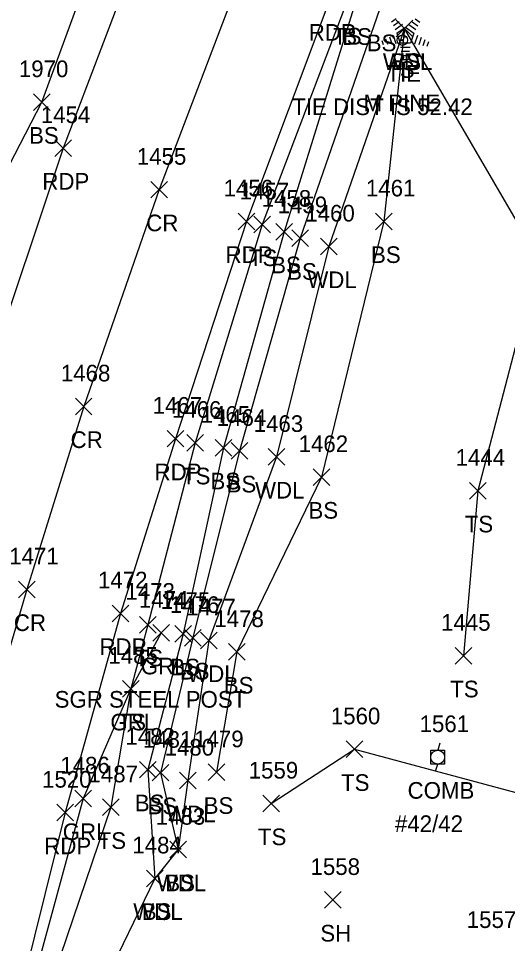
# Model space of a CAD drawing. Extents: x 1885914 to 1887218, y 756253 to 760620.
# Drawn here: x 1886460.8 to 1886519.5, y 759787.4 to 759898.5 of the extents above; entities that cross this region are included whole.
import ezdxf

# ---------------------------------------------------------------- set-up
doc = ezdxf.new("R2010")
doc.units = 0
for name, color, linetype in [('C_A', 7, 'Continuous'), ('C_C', 7, 'Continuous'), ('CBP', 7, 'Continuous'), ('L_A', 7, 'Continuous'), ('L_C', 7, 'Continuous'), ('L_I', 7, 'Continuous'), ('L_TIC', 7, 'Continuous'), ('LAWA', 7, 'Continuous'), ('LELB', 7, 'Continuous'), ('LTC', 7, 'Continuous'), ('P_A', 7, 'Continuous'), ('P_I', 7, 'Continuous'), ('P_TIC', 7, 'Continuous'), ('PET', 7, 'Continuous'), ('PRC', 7, 'Continuous'), ('R_A', 7, 'Continuous'), ('R_C', 7, 'Continuous'), ('R_I', 7, 'Continuous'), ('R_TIC', 7, 'Continuous'), ('RGR', 7, 'Continuous'), ('U_A', 7, 'Continuous'), ('U_C', 7, 'Continuous'), ('U_I', 7, 'Continuous'), ('UP', 7, 'Continuous')]:
    doc.layers.add(name, color=color, linetype=linetype)

msp = doc.modelspace()

# ---------------------------------------------------------------- linework, layer by layer
at = {"layer": 'CBP'}
for radius in [0.625, 0.0833]:
    msp.add_circle((1886506.91, 759895.92), radius, dxfattribs=at)
at = {"layer": 'L_TIC'}
for points in [[(1886506.15, 759896.34), (1886508.15, 759898.34)], [(1886508.15, 759896.34), (1886506.15, 759898.34)], [(1886506.15, 759896.34), (1886508.15, 759898.34)], [(1886508.15, 759896.34), (1886506.15, 759898.34)], [(1886462.57, 759887.48), (1886464.57, 759889.48)], [(1886464.57, 759887.48), (1886462.57, 759889.48)], [(1886489.04, 759872.78), (1886491.04, 759874.78)], [(1886491.04, 759872.78), (1886489.04, 759874.78)], [(1886503.69, 759873.15), (1886505.69, 759875.15)], [(1886505.69, 759873.15), (1886503.69, 759875.15)], [(1886491.69, 759871.91), (1886493.69, 759873.91)], [(1886493.69, 759871.91), (1886491.69, 759873.91)], [(1886493.61, 759871.13), (1886495.61, 759873.13)], [(1886495.61, 759871.13), (1886493.61, 759873.13)], [(1886497.06, 759870.13), (1886499.06, 759872.13)], [(1886499.06, 759870.13), (1886497.06, 759872.13)], [(1886481, 759846.55), (1886483, 759848.55)], [(1886483, 759846.55), (1886481, 759848.55)], [(1886484.39, 759845.95), (1886486.39, 759847.95)], [(1886486.39, 759845.95), (1886484.39, 759847.95)], [(1886486.33, 759845.58), (1886488.33, 759847.58)], [(1886488.33, 759845.58), (1886486.33, 759847.58)], [(1886490.77, 759844.85), (1886492.77, 759846.85)], [(1886492.77, 759844.85), (1886490.77, 759846.85)], [(1886496.17, 759842.43), (1886498.17, 759844.43)], [(1886498.17, 759842.43), (1886496.17, 759844.43)], [(1886514.99, 759840.78), (1886516.99, 759842.78)], [(1886516.99, 759840.78), (1886514.99, 759842.78)], [(1886475.31, 759824.69), (1886477.31, 759826.69)], [(1886477.31, 759824.69), (1886475.31, 759826.69)], [(1886479.56, 759823.59), (1886481.56, 759825.59)], [(1886481.56, 759823.59), (1886479.56, 759825.59)], [(1886480.7, 759823.1), (1886482.7, 759825.1)], [(1886482.7, 759823.1), (1886480.7, 759825.1)], [(1886482.62, 759822.8), (1886484.62, 759824.8)], [(1886484.62, 759822.8), (1886482.62, 759824.8)], [(1886485.99, 759821.41), (1886487.99, 759823.41)], [(1886487.99, 759821.41), (1886485.99, 759823.41)], [(1886513.24, 759820.96), (1886515.24, 759822.96)], [(1886515.24, 759820.96), (1886513.24, 759822.96)], [(1886473.25, 759816.99), (1886475.25, 759818.99)], [(1886475.25, 759816.99), (1886473.25, 759818.99)], [(1886500.13, 759809.72), (1886502.13, 759811.72)], [(1886502.13, 759809.72), (1886500.13, 759811.72)], [(1886475.3, 759807.27), (1886477.3, 759809.27)], [(1886477.3, 759807.27), (1886475.3, 759809.27)], [(1886476.83, 759806.91), (1886478.83, 759808.91)], [(1886478.83, 759806.91), (1886476.83, 759808.91)], [(1886483.57, 759806.96), (1886485.57, 759808.96)], [(1886485.57, 759806.96), (1886483.57, 759808.96)], [(1886480.1, 759805.96), (1886482.1, 759807.96)], [(1886482.1, 759805.96), (1886480.1, 759807.96)], [(1886470.86, 759802.75), (1886472.86, 759804.75)], [(1886472.86, 759802.75), (1886470.86, 759804.75)], [(1886490.13, 759803.2), (1886492.13, 759805.2)], [(1886492.13, 759803.2), (1886490.13, 759805.2)], [(1886478.96, 759797.66), (1886480.96, 759799.66)], [(1886480.96, 759797.66), (1886478.96, 759799.66)], [(1886478.96, 759797.66), (1886480.96, 759799.66)], [(1886480.96, 759797.66), (1886478.96, 759799.66)], [(1886476.13, 759794.21), (1886478.13, 759796.21)], [(1886478.13, 759794.21), (1886476.13, 759796.21)], [(1886476.13, 759794.21), (1886478.13, 759796.21)], [(1886478.13, 759794.21), (1886476.13, 759796.21)], [(1886497.55, 759791.62), (1886499.55, 759793.62)], [(1886499.55, 759791.62), (1886497.55, 759793.62)]]:
    msp.add_lwpolyline(points, dxfattribs=at)
at = {"layer": 'LAWA'}
msp.add_lwpolyline([(1886523.26, 759869.7), (1886507.15, 759897.34), (1886498.06, 759871.13), (1886491.77, 759845.85), (1886483.62, 759823.8), (1886481.1, 759806.96), (1886479.96, 759798.66), (1886477.13, 759795.21), (1886470.77, 759782.07), (1886465.64, 759760.08), (1886461.33, 759737.18), (1886457.67, 759707.39), (1886455.06, 759684.97), (1886454.35, 759663.94), (1886455.07, 759641.46), (1886456.61, 759622.06), (1886456.79, 759611.09), (1886458.12, 759603.52), (1886460.31, 759591.25), (1886468.58, 759565.01)], dxfattribs=at)
at = {"layer": 'LELB'}
for points in [[(1886725.27, 760338.09), (1886712.33, 760310.28), (1886698.46, 760286.41), (1886683.25, 760252.31), (1886665.56, 760220.6), (1886649.26, 760186.3), (1886631.93, 760155.48), (1886614.95, 760123.77), (1886599.48, 760094.94), (1886586.46, 760070.53), (1886572.04, 760041.07), (1886559.72, 760022.59), (1886545.87, 759996.97), (1886529.41, 759963.14), (1886510.6, 759921.25), (1886501.24, 759900.36), (1886492.69, 759872.91), (1886485.39, 759846.95), (1886480.56, 759824.59), (1886476.3, 759808.27), (1886477.13, 759795.21)], [(1886435.82, 759833.71), (1886443.92, 759843.16), (1886452.31, 759861.14), (1886457.66, 759877.13), (1886463.57, 759888.48), (1886474.59, 759918.53), (1886493.94, 759963.02), (1886508.21, 759990.58), (1886529.58, 760040.14)], [(1886559.72, 760022.59), (1886549.4, 759996.33), (1886532.08, 759961.59), (1886524, 759917.34), (1886512.94, 759920.8), (1886504.17, 759899.59), (1886494.61, 759872.13), (1886487.33, 759846.58), (1886481.7, 759824.1), (1886477.83, 759807.91), (1886479.96, 759798.66)], [(1886564.69, 760023.37), (1886556.81, 759992.84), (1886551.99, 759948.71), (1886542, 759918.15), (1886528.59, 759884.81), (1886523.26, 759869.7), (1886515.99, 759841.78), (1886514.24, 759821.96)], [(1886527.64, 759964.02), (1886508.85, 759921.99), (1886500.17, 759900.4), (1886490.04, 759873.78), (1886482, 759847.55), (1886476.31, 759825.69), (1886474.25, 759817.99), (1886471.86, 759803.75), (1886464.28, 759781.47), (1886459.74, 759761.62), (1886455.11, 759738.34), (1886453.91, 759709.07), (1886450.32, 759686.96), (1886450.55, 759665.25), (1886450.92, 759642.65), (1886453.45, 759622.64), (1886456.79, 759611.09)], [(1886507.15, 759897.34), (1886504.69, 759874.15), (1886497.17, 759843.43), (1886486.99, 759822.41), (1886484.57, 759807.96)], [(1886491.13, 759804.2), (1886501.13, 759810.72), (1886522.18, 759805.09), (1886544.57, 759789.63), (1886568.21, 759770.94), (1886581.11, 759761.41), (1886584.27, 759751.77)]]:
    msp.add_lwpolyline(points, dxfattribs=at)
at = {"layer": 'LTC'}
for p, q in [((1886505.61, 759898.13), (1886506.14, 759898.52)), ((1886505.82, 759897.67), (1886506.52, 759898.18)), ((1886506.03, 759897.2), (1886506.91, 759897.84)), ((1886508.06, 759898.14), (1886508.74, 759897.65)), ((1886508.43, 759898.49), (1886508.98, 759898.09)), ((1886506.25, 759896.75), (1886507.27, 759897.48)), ((1886506.25, 759896.75), (1886506.64, 759895.55)), ((1886507.27, 759897.48), (1886508.26, 759896.76)), ((1886507.69, 759897.79), (1886508.5, 759897.2)), ((1886508.26, 759896.76), (1886507.87, 759895.55)), ((1886504.43, 759895.88), (1886504.59, 759895.41)), ((1886504.89, 759896.09), (1886505.1, 759895.44)), ((1886505.34, 759896.31), (1886505.62, 759895.47)), ((1886505.8, 759896.53), (1886506.13, 759895.51)), ((1886508.7, 759896.48), (1886508.36, 759895.44)), ((1886509.15, 759896.23), (1886508.86, 759895.35)), ((1886509.59, 759895.98), (1886509.35, 759895.25)), ((1886510.03, 759895.73), (1886509.85, 759895.16)), ((1886507.87, 759895.55), (1886506.64, 759895.55)), ((1886507.83, 759895.05), (1886506.69, 759895.05)), ((1886507.75, 759894.55), (1886506.76, 759894.55)), ((1886507.67, 759894.05), (1886506.83, 759894.05)), ((1886507.58, 759893.55), (1886506.91, 759893.55))]:
    msp.add_line(p, q, dxfattribs=at)
at = {"layer": 'P_TIC'}
for points in [[(1886465.13, 759881.96), (1886467.13, 759883.96)], [(1886467.13, 759881.96), (1886465.13, 759883.96)], [(1886476.68, 759876.96), (1886478.68, 759878.96)], [(1886478.68, 759876.96), (1886476.68, 759878.96)], [(1886487.16, 759873.15), (1886489.16, 759875.15)], [(1886489.16, 759873.15), (1886487.16, 759875.15)], [(1886467.59, 759850.92), (1886469.59, 759852.92)], [(1886469.59, 759850.92), (1886467.59, 759852.92)], [(1886478.62, 759847.04), (1886480.62, 759849.04)], [(1886480.62, 759847.04), (1886478.62, 759849.04)], [(1886460.77, 759828.93), (1886462.77, 759830.93)], [(1886462.77, 759828.93), (1886460.77, 759830.93)], [(1886472, 759826.05), (1886474, 759828.05)], [(1886474, 759826.05), (1886472, 759828.05)], [(1886465.37, 759802.11), (1886467.37, 759804.11)], [(1886467.37, 759802.11), (1886465.37, 759804.11)]]:
    msp.add_lwpolyline(points, dxfattribs=at)
at = {"layer": 'PET'}
for points in [[(1886505.21, 759975.04), (1886485.32, 759931.76), (1886475.82, 759908.45), (1886466.13, 759882.96), (1886456.93, 759855.61), (1886449.99, 759833.06), (1886442.98, 759808.26), (1886435.87, 759778.49), (1886430.37, 759752.23), (1886424.92, 759721.57), (1886422.03, 759696.27), (1886420.3, 759670.71), (1886419.91, 759641.82), (1886421.23, 759616.47), (1886424.6, 759585.72), (1886430.09, 759554.32), (1886435.19, 759528.63), (1886443.72, 759490.84), (1886451.63, 759459.71), (1886459.13, 759429.12), (1886468.69, 759393.26), (1886479.71, 759351.07), (1886485.06, 759331.17)], [(1886526.14, 759964.92), (1886507.07, 759922.75), (1886498.17, 759900.86), (1886488.16, 759874.15), (1886479.62, 759848.04), (1886473, 759827.05), (1886466.37, 759803.11), (1886458.99, 759773.42), (1886453.36, 759746.97), (1886448.76, 759720.11), (1886445.71, 759693.61), (1886444.44, 759668.96), (1886443.78, 759643.55), (1886445.31, 759617.59), (1886448.26, 759589.04), (1886453.63, 759558.69), (1886458.27, 759533.55), (1886466.8, 759496), (1886474.35, 759464.49), (1886481.64, 759434.54), (1886491.18, 759398.8), (1886502.68, 759358.39), (1886508.23, 759337.95)]]:
    msp.add_lwpolyline(points, dxfattribs=at)
at = {"layer": 'PRC'}
msp.add_lwpolyline([(1886516.05, 759969.43), (1886496.99, 759926.69), (1886487.66, 759904.2), (1886477.68, 759877.96), (1886468.59, 759851.92), (1886461.77, 759829.93), (1886454.6, 759805.62), (1886447.16, 759775.82), (1886441.74, 759748.8), (1886436.89, 759720.56), (1886434.02, 759695.25), (1886432.32, 759669.09), (1886432.26, 759642.82), (1886433.77, 759616.6), (1886436.98, 759587.84), (1886441.74, 759556.93), (1886446.53, 759531.43), (1886454.86, 759493.34), (1886462.57, 759461.76), (1886470.69, 759431.8), (1886480.02, 759395.82), (1886491.53, 759354.96), (1886496.99, 759335.08)], dxfattribs=at)
at = {"layer": 'R_TIC'}
for points in [[(1886476.91, 759823.72), (1886478.91, 759825.72)], [(1886478.91, 759823.72), (1886476.91, 759825.72)], [(1886473.25, 759816.99), (1886475.25, 759818.99)], [(1886475.25, 759816.99), (1886473.25, 759818.99)], [(1886467.53, 759803.81), (1886469.53, 759805.81)], [(1886469.53, 759803.81), (1886467.53, 759805.81)]]:
    msp.add_lwpolyline(points, dxfattribs=at)
at = {"layer": 'RGR'}
msp.add_lwpolyline([(1886477.91, 759824.72), (1886474.25, 759817.99), (1886468.53, 759804.81), (1886462.22, 759781.75), (1886457.79, 759761.55), (1886452.9, 759737.77), (1886448.54, 759709.05), (1886446.73, 759687.2), (1886445.74, 759665.88), (1886445.12, 759642.63), (1886445.94, 759621.97), (1886446.09, 759621.22), (1886448.56, 759607.2), (1886453.2, 759590.37)], dxfattribs=at)
at = {"layer": 'UP'}
for p, q in [((1886511.4, 759811.45), (1886511.15, 759810.61)), ((1886510.31, 759808.95), (1886510.31, 759810.61)), ((1886510.31, 759810.61), (1886511.98, 759810.61)), ((1886511.98, 759810.61), (1886511.98, 759808.95)), ((1886511.98, 759808.95), (1886510.31, 759808.95)), ((1886510.9, 759808.11), (1886511.15, 759808.95)), ((1886511.15, 759809.78), (1886511.15, 759809.78))]:
    msp.add_line(p, q, dxfattribs=at)
msp.add_circle((1886511.15, 759809.78), 0.833, dxfattribs=at)

# ---------------------------------------------------------------- texts
at = {"layer": 'C_A'}
msp.add_text('TIE', height=2, dxfattribs=at).set_placement((1886504.99, 759890.92))
at = {"layer": 'C_C'}
msp.add_text('TIE DIST IS 52.42', height=2, dxfattribs=at).set_placement((1886493.66, 759886.92))
at = {"layer": 'L_A'}
for s, p in [('TS', (1886498.58, 759895.4)), ('BS', (1886499.68, 759895.36)), ('BS', (1886502.61, 759894.59)), ('WDL', (1886504.56, 759892.34)), ('BS', (1886505.59, 759892.34)), ('S', (1886506.59, 759891.39)), ('BS', (1886462.02, 759883.48)), ('BS', (1886503.13, 759869.15)), ('TS', (1886488.45, 759868.78)), ('BS', (1886491.13, 759867.91)), ('BS', (1886493.05, 759867.13)), ('WDL', (1886495.47, 759866.13)), ('TS', (1886480.41, 759842.55)), ('BS', (1886483.83, 759841.95)), ('BS', (1886485.77, 759841.58)), ('WDL', (1886489.19, 759840.85)), ('BS', (1886495.61, 759838.43)), ('TS', (1886514.4, 759836.78)), ('TS', (1886474.72, 759820.69)), ('BS', (1886479, 759819.59)), ('BS', (1886480.14, 759819.1)), ('WDL', (1886481.04, 759818.8)), ('BS', (1886485.43, 759817.41)), ('TS', (1886512.65, 759816.96)), ('TS', (1886472.66, 759812.99)), ('TS', (1886499.53, 759805.72)), ('BS', (1886474.74, 759803.27)), ('BS', (1886476.27, 759802.91)), ('BS', (1886483.01, 759802.96)), ('WDL', (1886478.51, 759801.96)), ('TS', (1886489.54, 759799.2)), ('TS', (1886470.27, 759798.75)), ('WDL', (1886477.37, 759793.66)), ('BS', (1886478.4, 759793.66)), ('BS', (1886475.57, 759790.21)), ('WDL', (1886474.55, 759790.21)), ('SH', (1886497.04, 759787.62))]:
    msp.add_text(s, height=2, dxfattribs=at).set_placement(p)
at = {"layer": 'L_C'}
msp.add_text('M PINE', height=2, dxfattribs=at).set_placement((1886502.23, 759887.39))
at = {"layer": 'L_I'}
for s, p in [('1970', (1886460.8, 759891.48)), ('1461', (1886502.52, 759877.15)), ('1457', (1886487.35, 759876.78)), ('1458', (1886489.99, 759875.91)), ('1459', (1886491.91, 759875.13)), ('1460', (1886495.23, 759874.13)), ('1466', (1886479.2, 759850.55)), ('1465', (1886482.65, 759849.95)), ('1464', (1886484.59, 759849.58)), ('1463', (1886489.03, 759848.85)), ('1462', (1886494.43, 759846.43)), ('1444', (1886513.3, 759844.78)), ('1473', (1886473.61, 759828.69)), ('1475', (1886477.86, 759827.59)), ('1476', (1886478.95, 759827.1)), ('1477', (1886480.93, 759826.8)), ('1478', (1886484.3, 759825.41)), ('1445', (1886511.55, 759824.96)), ('1485', (1886471.56, 759820.99)), ('1560', (1886498.3, 759813.72)), ('1482', (1886473.61, 759811.27)), ('1481', (1886475.7, 759810.91)), ('1479', (1886481.87, 759810.96)), ('1480', (1886478.32, 759809.96)), ('1559', (1886488.43, 759807.2)), ('1487', (1886469.17, 759806.75)), ('1483', (1886477.26, 759801.66)), ('1483', (1886477.26, 759801.66)), ('1484', (1886474.44, 759798.21)), ('1484', (1886474.44, 759798.21)), ('1558', (1886495.86, 759795.62)), ('1557', (1886514.64, 759789.25))]:
    msp.add_text(s, height=2, dxfattribs=at).set_placement(p)
at = {"layer": 'LTC'}
msp.add_text('.', height=1.04, rotation=270, dxfattribs=at).set_placement((1886507.15, 759896.49))
at = {"layer": 'P_A'}
for s, p in [('RDP', (1886495.65, 759895.86)), ('RDP', (1886463.62, 759877.96)), ('CR', (1886476.11, 759872.96)), ('RDP', (1886485.65, 759869.15)), ('CR', (1886467.02, 759846.92)), ('RDP', (1886477.11, 759843.04)), ('CR', (1886460.2, 759824.93)), ('RDP', (1886470.49, 759822.05)), ('RDP', (1886463.85, 759798.11))]:
    msp.add_text(s, height=2, dxfattribs=at).set_placement(p)
at = {"layer": 'P_I'}
for s, p in [('1454', (1886463.44, 759885.96)), ('1455', (1886474.98, 759880.96)), ('1456', (1886485.41, 759877.15)), ('1468', (1886465.85, 759854.92)), ('1467', (1886476.88, 759851.04)), ('1471', (1886459.64, 759832.93)), ('1472', (1886470.31, 759830.05)), ('1520', (1886463.59, 759806.11))]:
    msp.add_text(s, height=2, dxfattribs=at).set_placement(p)
at = {"layer": 'R_A'}
for p in [(1886475.46, 759819.72), (1886471.8, 759812.99), (1886466.07, 759799.81)]:
    msp.add_text('GRL', height=2, dxfattribs=at).set_placement(p)
at = {"layer": 'R_C'}
msp.add_text('SGR STEEL POST', height=2, dxfattribs=at).set_placement((1886465.1, 759815.72))
at = {"layer": 'R_I'}
for s, p in [('1474', (1886475.22, 759827.72)), ('1485', (1886471.56, 759820.99)), ('1486', (1886465.78, 759807.81))]:
    msp.add_text(s, height=2, dxfattribs=at).set_placement(p)
at = {"layer": 'U_A'}
msp.add_text('COMB', height=2, dxfattribs=at).set_placement((1886507.53, 759804.78))
at = {"layer": 'U_C'}
msp.add_text('#42/42', height=2, dxfattribs=at).set_placement((1886506.01, 759800.78))
at = {"layer": 'U_I'}
msp.add_text('1561', height=2, dxfattribs=at).set_placement((1886508.97, 759812.78))

doc.saveas('drawing.dxf')
